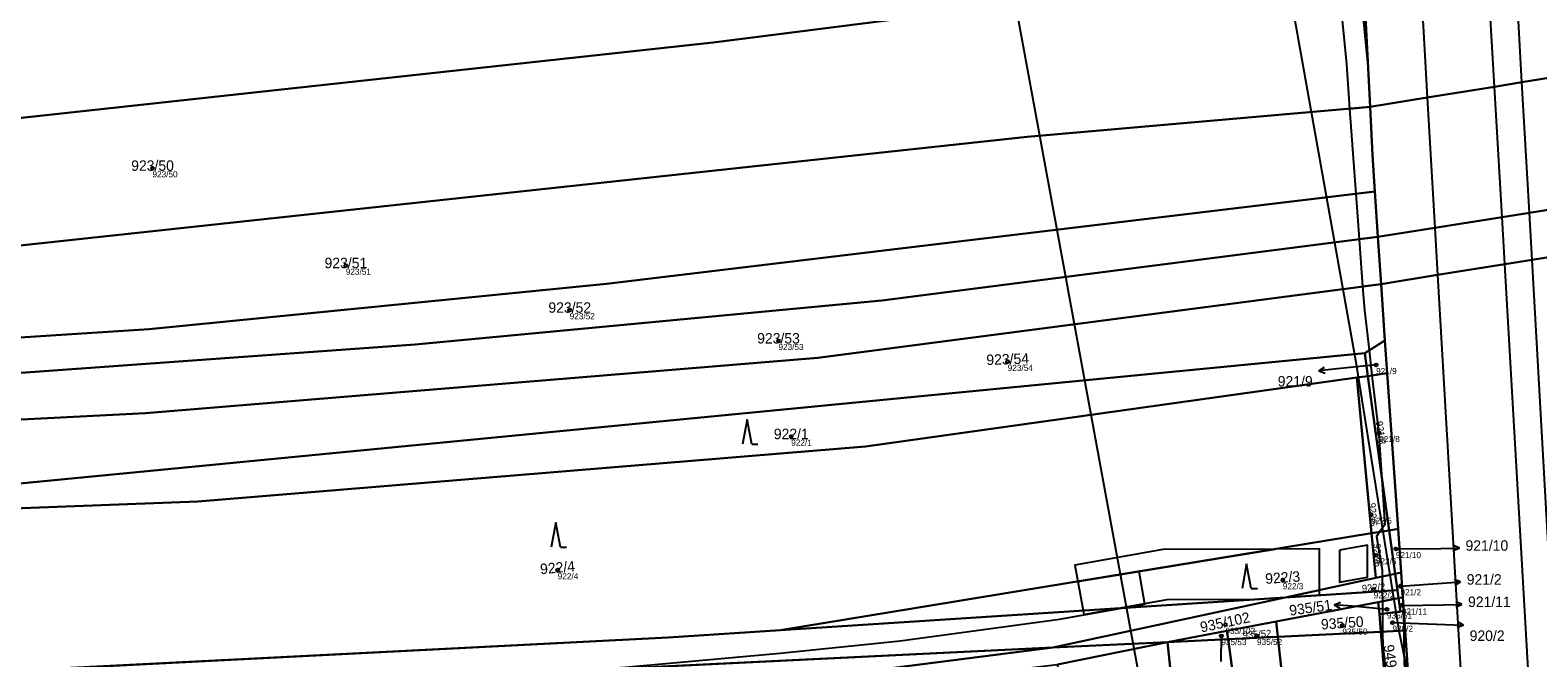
# Model space of a CAD drawing. Extents: x -603967 to -594699, y -1179315 to -1165625.
# Drawn here: x -596123.7 to -595878.2, y -1172335.5 to -1172233.4 of the extents above; entities that cross this region are included whole.
import ezdxf

# ---------------------------------------------------------------- set-up
doc = ezdxf.new("R2010")
doc.units = 0
for name, color, linetype in [('Definiční body', 7, 'Continuous'), ('Hranice parcel', 7, 'Continuous'), ('Parcelní čísla', 7, 'Continuous'), ('Polygon parcely', 7, 'Continuous'), ('Pop  PČ popisy', 7, 'Continuous'), ('Poz předměty', 7, 'Continuous'), ('Vnitřní kresba', 7, 'Continuous'), ('Věcná břemena k části', 7, 'Continuous'), ('Značky kultur', 7, 'Continuous')]:
    doc.layers.add(name, color=color, linetype=linetype)

msp = doc.modelspace()

# ---------------------------------------------------------------- linework, layer by layer
at = {"layer": 'Definiční body'}
for centre in [(-596103.76, -1172255.84994), (-596072.28, -1172271.69994), (-596035.83, -1172278.94994), (-596001.84, -1172283.95994), (-595964.51, -1172287.34994), (-595904.53, -1172287.87994), (-595999.76, -1172299.52994), (-595904.03, -1172298.93994), (-595905.33, -1172312.22994), (-595904.56, -1172318.84994), (-595901.31, -1172317.82994), (-596037.78, -1172321.27994), (-595919.72, -1172322.89994), (-595900.56, -1172323.87994), (-595904.92, -1172324.37994), (-595902.76, -1172327.66994), (-595900.33, -1172327.01994), (-595929.06, -1172330.16994), (-595910.02, -1172330.28994), (-595901.87, -1172329.80994), (-595929.73, -1172331.98994), (-595923.92, -1172331.97994)]:
    msp.add_circle(centre, 0.25, dxfattribs=at)
at = {"layer": 'Hranice parcel'}
for p, q in [((-595905.51, -1172245.87), (-595906.57, -1172224.82)), ((-595904.23, -1172267.03), (-595904.72, -1172259.65)), ((-595903.73, -1172274.7), (-595904.23, -1172267.03)), ((-595903.09, -1172283.88), (-595903.73, -1172274.7)), ((-595903.09, -1172283.88), (-595906.39, -1172285.93)), ((-595902.72, -1172289.23), (-595903.09, -1172283.88)), ((-595906.39, -1172285.93), (-596193.74, -1172313.8)), ((-595906.39, -1172285.93), (-595905.87, -1172289.68)), ((-595907.65, -1172289.93), (-595905.87, -1172289.68)), ((-595902.72, -1172289.23), (-595905.87, -1172289.68)), ((-595905.87, -1172289.68), (-595902.4, -1172314.8)), ((-595900.95, -1172314.56), (-595902.72, -1172289.23)), ((-595905.26, -1172315.27), (-595907.65, -1172289.93)), ((-595905.26, -1172315.27), (-596001.53, -1172331.07)), ((-595905.26, -1172315.27), (-595902.4, -1172314.8)), ((-595904.58, -1172322.55), (-595905.26, -1172315.27)), ((-595902.4, -1172314.8), (-595900.95, -1172314.56)), ((-595902.4, -1172314.8), (-595901.42, -1172321.87)), ((-595900.45, -1172321.66), (-595900.95, -1172314.56)), ((-595904.58, -1172322.55), (-595919.31, -1172325.73)), ((-595901.42, -1172321.87), (-595904.58, -1172322.55)), ((-595900.45, -1172321.66), (-595901.42, -1172321.87)), ((-595901.42, -1172321.87), (-595901.05, -1172324.54)), ((-595900.17, -1172325.7), (-595900.45, -1172321.66)), ((-596001.53, -1172331.07), (-595919.31, -1172325.73)), ((-595957.14, -1172333.89), (-595919.31, -1172325.73)), ((-595904.21, -1172326.47), (-595920.79, -1172329.63)), ((-595919.31, -1172325.73), (-595901.05, -1172324.54)), ((-595900.87, -1172325.83), (-595904.21, -1172326.47)), ((-595903.99, -1172328.44), (-595904.21, -1172326.47)), ((-595901.05, -1172324.54), (-595900.87, -1172325.83)), ((-595900.87, -1172325.83), (-595900.17, -1172325.7)), ((-595900.87, -1172325.83), (-595900.57, -1172328.01)), ((-595900.01, -1172327.94), (-595900.17, -1172325.7)), ((-595900.57, -1172328.01), (-595903.99, -1172328.44)), ((-595903.99, -1172328.44), (-595903.75, -1172331.3)), ((-595900.01, -1172327.94), (-595900.57, -1172328.01)), ((-595899.79, -1172331.11), (-595900.01, -1172327.94)), ((-596019.77, -1172332.25), (-596001.53, -1172331.07)), ((-595928.82, -1172331.16), (-595938.51, -1172332.99)), ((-595920.79, -1172329.63), (-595928.82, -1172331.16)), ((-595928.82, -1172331.16), (-595928.64, -1172332.51)), ((-595920.79, -1172329.63), (-595920.52, -1172332.12)), ((-595920.52, -1172332.12), (-595903.75, -1172331.3)), ((-595903.75, -1172331.3), (-595895.47, -1172399.23)), ((-596194.13, -1172341.1), (-596019.77, -1172332.25)), ((-596158.17, -1172343.65), (-595957.14, -1172333.89)), ((-595957.14, -1172333.89), (-595938.51, -1172332.99)), ((-595956.41, -1172336.65), (-595938.51, -1172332.99)), ((-595938.51, -1172332.99), (-595928.64, -1172332.51)), ((-595928.64, -1172332.51), (-595920.52, -1172332.12))]:
    msp.add_line(p, q, dxfattribs=at)
for points in [[(-595906.57, -1172224.82), (-595953.9, -1172227.9), (-596012.47, -1172235.41), (-596191.41, -1172254.87)], [(-595905.51, -1172245.87), (-595896.2, -1172244.36), (-595885.25, -1172242.59), (-595880.78, -1172241.87), (-595870.02, -1172240.13), (-595859.8, -1172238.47)], [(-596192.75, -1172275.68), (-595961.33, -1172250.76), (-595905.51, -1172245.87)], [(-595904.72, -1172259.65), (-595905.11, -1172253.75), (-595905.51, -1172245.87)], [(-596193.53, -1172287.79), (-596104.28, -1172282.03), (-596029.82, -1172274.66), (-595904.72, -1172259.65)], [(-595904.23, -1172267.03), (-595894.97, -1172265.55), (-595884.02, -1172263.8), (-595879.58, -1172263.09), (-595868.78, -1172261.36), (-595858.57, -1172259.73)], [(-596193.94, -1172294.09), (-596060.97, -1172284.56), (-595984.98, -1172277.39), (-595904.23, -1172267.03)], [(-595858.12, -1172267.42), (-595868.33, -1172269.05), (-595879.14, -1172270.77), (-595883.58, -1172271.48), (-595894.52, -1172273.23), (-595903.73, -1172274.7)], [(-596194.34, -1172300.28), (-596104.92, -1172295.74), (-595995.41, -1172286.7), (-595903.73, -1172274.7)], [(-596193.74, -1172313.8), (-596096.36, -1172310.09), (-595987.69, -1172301.14), (-595907.65, -1172289.93)], [(-595903.75, -1172331.3), (-595900.85, -1172331.16), (-595899.79, -1172331.11)], [(-595892.57, -1172559.03), (-595889.91, -1172548.74), (-595889.32, -1172536.66), (-595894.96, -1172434.47), (-595903.75, -1172331.3)], [(-595895.47, -1172399.23), (-595899.29, -1172338.29), (-595899.79, -1172331.11)], [(-596157.69, -1172348), (-596034.81, -1172343.77), (-595957.14, -1172333.89)], [(-595918.41, -1172542.08), (-595925.89, -1172452.77), (-595938.51, -1172332.99)], [(-595906.51, -1172549.65), (-595911.21, -1172477.31), (-595920.32, -1172393.96), (-595928.64, -1172332.51)], [(-595899.79, -1172554.17), (-595905.94, -1172465.46), (-595920.52, -1172332.12)]]:
    msp.add_lwpolyline(points, dxfattribs=at)
at = {"layer": 'Polygon parcely'}
for points in [[(-595906.57, -1172224.82), (-595907.75, -1172201.36), (-596008.1, -1172212.73), (-596189.99, -1172232.87), (-596191.41, -1172254.87), (-596012.47, -1172235.41), (-595953.9, -1172227.9)], [(-595880.78, -1172241.87), (-595870.02, -1172240.13), (-595859.8, -1172238.47), (-595861.02, -1172217.5), (-595871.25, -1172219.15), (-595881.97, -1172220.87), (-595886.47, -1172221.59), (-595897.42, -1172223.35), (-595906.57, -1172224.82), (-595905.51, -1172245.87), (-595896.2, -1172244.36), (-595885.25, -1172242.59)], [(-596191.41, -1172254.87), (-596192.75, -1172275.68), (-595961.33, -1172250.76), (-595905.51, -1172245.87), (-595906.57, -1172224.82), (-595953.9, -1172227.9), (-596012.47, -1172235.41)], [(-595884.02, -1172263.8), (-595879.58, -1172263.09), (-595868.78, -1172261.36), (-595858.57, -1172259.73), (-595858.94, -1172253.33), (-595859.8, -1172238.47), (-595870.02, -1172240.13), (-595880.78, -1172241.87), (-595885.25, -1172242.59), (-595896.2, -1172244.36), (-595905.51, -1172245.87), (-595905.11, -1172253.75), (-595904.72, -1172259.65), (-595904.23, -1172267.03), (-595894.97, -1172265.55)], [(-596193.53, -1172287.79), (-596104.28, -1172282.03), (-596029.82, -1172274.66), (-595904.72, -1172259.65), (-595905.11, -1172253.75), (-595905.51, -1172245.87), (-595961.33, -1172250.76), (-596192.75, -1172275.68)], [(-595904.23, -1172267.03), (-595904.72, -1172259.65), (-596029.82, -1172274.66), (-596104.28, -1172282.03), (-596193.53, -1172287.79), (-596193.94, -1172294.09), (-596060.97, -1172284.56), (-595984.98, -1172277.39)], [(-595858.12, -1172267.42), (-595858.57, -1172259.73), (-595868.78, -1172261.36), (-595879.58, -1172263.09), (-595884.02, -1172263.8), (-595894.97, -1172265.55), (-595904.23, -1172267.03), (-595903.73, -1172274.7), (-595894.52, -1172273.23), (-595883.58, -1172271.48), (-595879.14, -1172270.77), (-595868.33, -1172269.05)], [(-595903.73, -1172274.7), (-595904.23, -1172267.03), (-595984.98, -1172277.39), (-596060.97, -1172284.56), (-596193.94, -1172294.09), (-596194.34, -1172300.28), (-596104.92, -1172295.74), (-595995.41, -1172286.7)], [(-595903.09, -1172283.88), (-595903.73, -1172274.7), (-595995.41, -1172286.7), (-596104.92, -1172295.74), (-596194.34, -1172300.28), (-596195.22, -1172313.87), (-596193.74, -1172313.8), (-595906.39, -1172285.93)], [(-595902.72, -1172289.23), (-595903.09, -1172283.88), (-595906.39, -1172285.93), (-595905.87, -1172289.68)], [(-595905.87, -1172289.68), (-595906.39, -1172285.93), (-596193.74, -1172313.8), (-596096.36, -1172310.09), (-595987.69, -1172301.14), (-595907.65, -1172289.93)], [(-595905.26, -1172315.27), (-595902.4, -1172314.8), (-595905.87, -1172289.68), (-595907.65, -1172289.93)], [(-595902.4, -1172314.8), (-595900.95, -1172314.56), (-595902.72, -1172289.23), (-595905.87, -1172289.68)], [(-595905.26, -1172315.27), (-595907.65, -1172289.93), (-595987.69, -1172301.14), (-596096.36, -1172310.09), (-596193.74, -1172313.8), (-596194.13, -1172341.1), (-596019.77, -1172332.25), (-596001.53, -1172331.07)], [(-596001.53, -1172331.07), (-595919.31, -1172325.73), (-595904.58, -1172322.55), (-595905.26, -1172315.27)], [(-595901.42, -1172321.87), (-595902.4, -1172314.8), (-595905.26, -1172315.27), (-595904.58, -1172322.55)], [(-595901.42, -1172321.87), (-595900.45, -1172321.66), (-595900.95, -1172314.56), (-595902.4, -1172314.8)], [(-595919.31, -1172325.73), (-595901.05, -1172324.54), (-595901.42, -1172321.87), (-595904.58, -1172322.55)], [(-595901.42, -1172321.87), (-595901.05, -1172324.54), (-595900.87, -1172325.83), (-595900.17, -1172325.7), (-595900.45, -1172321.66)], [(-596194.86, -1172345.53), (-596158.17, -1172343.65), (-595957.14, -1172333.89), (-595919.31, -1172325.73), (-596001.53, -1172331.07), (-596019.77, -1172332.25), (-596194.13, -1172341.1), (-596196.99, -1172341.21), (-596199.78, -1172341.32), (-596198.52, -1172345.99)], [(-595957.14, -1172333.89), (-595938.51, -1172332.99), (-595928.82, -1172331.16), (-595920.79, -1172329.63), (-595904.21, -1172326.47), (-595900.87, -1172325.83), (-595901.05, -1172324.54), (-595919.31, -1172325.73)], [(-595920.52, -1172332.12), (-595903.75, -1172331.3), (-595903.99, -1172328.44), (-595904.21, -1172326.47), (-595920.79, -1172329.63)], [(-595900.87, -1172325.83), (-595904.21, -1172326.47), (-595903.99, -1172328.44), (-595900.57, -1172328.01)], [(-595900.57, -1172328.01), (-595900.01, -1172327.94), (-595900.17, -1172325.7), (-595900.87, -1172325.83)], [(-595900.01, -1172327.94), (-595900.57, -1172328.01), (-595903.99, -1172328.44), (-595903.75, -1172331.3), (-595900.85, -1172331.16), (-595899.79, -1172331.11)], [(-595928.82, -1172331.16), (-595938.51, -1172332.99), (-595928.64, -1172332.51)], [(-595928.64, -1172332.51), (-595920.52, -1172332.12), (-595920.79, -1172329.63), (-595928.82, -1172331.16)], [(-595894.96, -1172434.47), (-595903.75, -1172331.3), (-595920.52, -1172332.12), (-595905.94, -1172465.46), (-595899.79, -1172554.17), (-595892.57, -1172559.03), (-595889.91, -1172548.74), (-595889.32, -1172536.66)], [(-595895.47, -1172399.23), (-595899.29, -1172338.29), (-595899.79, -1172331.11), (-595900.85, -1172331.16), (-595903.75, -1172331.3)], [(-595887.08, -1172537.79), (-595893.23, -1172433.55), (-595894.94, -1172407.61), (-595895.47, -1172399.23), (-595903.75, -1172331.3), (-595894.96, -1172434.47), (-595889.32, -1172536.66), (-595889.91, -1172548.74), (-595892.57, -1172559.03), (-595890.44, -1172561.15), (-595889.81, -1172560.41), (-595887.37, -1172550.11)], [(-596157.69, -1172348), (-596034.81, -1172343.77), (-595957.14, -1172333.89), (-596158.17, -1172343.65)], [(-595982.23, -1172340.15), (-595973.49, -1172338.64), (-595956.41, -1172336.65), (-595938.51, -1172332.99), (-595957.14, -1172333.89), (-596034.81, -1172343.77), (-596157.69, -1172348), (-596157.31, -1172351.36), (-596143.3, -1172350.24), (-596136.49, -1172350.13), (-596123.02, -1172349.7), (-596110.99, -1172349.51), (-596103.83, -1172349.38), (-596096.98, -1172349.13), (-596089.05, -1172348.79), (-596071.19, -1172348.02), (-596052.73, -1172347.42), (-596034.37, -1172346.55), (-596027.89, -1172345.98), (-596021.5, -1172345.1), (-596013.26, -1172344.03), (-596006.34, -1172343.33), (-595998.25, -1172342.44), (-595990.99, -1172341.19)], [(-595918.41, -1172542.08), (-595925.89, -1172452.77), (-595938.51, -1172332.99), (-595956.41, -1172336.65), (-595938.08, -1172531.05)], [(-595920.32, -1172393.96), (-595928.64, -1172332.51), (-595938.51, -1172332.99), (-595925.89, -1172452.77), (-595918.41, -1172542.08), (-595914.5, -1172544.27), (-595906.51, -1172549.65), (-595911.21, -1172477.31)], [(-595899.79, -1172554.17), (-595905.94, -1172465.46), (-595920.52, -1172332.12), (-595928.64, -1172332.51), (-595920.32, -1172393.96), (-595911.21, -1172477.31), (-595906.51, -1172549.65)]]:
    msp.add_lwpolyline(points, close=True, dxfattribs=at)
msp.add_lwpolyline([(-595868.33, -1172269.05), (-595879.14, -1172270.77), (-595883.58, -1172271.48), (-595894.52, -1172273.23), (-595903.73, -1172274.7), (-595903.09, -1172283.88), (-595902.72, -1172289.23), (-595900.95, -1172314.56), (-595900.45, -1172321.66), (-595900.17, -1172325.7), (-595900.01, -1172327.94), (-595899.79, -1172331.11), (-595899.29, -1172338.29), (-595895.47, -1172399.23), (-595894.94, -1172407.61), (-595884.6, -1172495.44), (-595881.58, -1172567.78), (-595887.7, -1172563.88), (-595887.85, -1172569.82), (-595877.77, -1172576.26)], dxfattribs=at)
at = {"layer": 'Pop  PČ popisy'}
for p, q in [((-595913.875, -1172288.834), (-595912.931, -1172288.231)), ((-595910.89, -1172288.52), (-595913.875, -1172288.834)), ((-595913.875, -1172288.834), (-595912.826, -1172289.227)), ((-595904.53, -1172287.88), (-595910.89, -1172288.52)), ((-595901.31, -1172317.83), (-595893.97, -1172317.73)), ((-595893.97, -1172317.73), (-595890.969, -1172317.678)), ((-595890.969, -1172317.678), (-595891.98, -1172317.194)), ((-595890.969, -1172317.678), (-595891.962, -1172318.196)), ((-595900.56, -1172323.88), (-595893.76, -1172323.41)), ((-595893.76, -1172323.41), (-595890.766, -1172323.201)), ((-595890.766, -1172323.201), (-595891.8, -1172322.771)), ((-595890.766, -1172323.201), (-595891.73, -1172323.77)), ((-595911.38, -1172326.898), (-595910.338, -1172326.487)), ((-595890.559, -1172326.848), (-595891.57, -1172326.364)), ((-595908.39, -1172327.16), (-595911.38, -1172326.898)), ((-595911.38, -1172326.898), (-595910.426, -1172327.485)), ((-595902.76, -1172327.67), (-595908.39, -1172327.16)), ((-595900.33, -1172327.02), (-595893.56, -1172326.9)), ((-595893.56, -1172326.9), (-595890.559, -1172326.848)), ((-595890.559, -1172326.848), (-595891.552, -1172327.366)), ((-595901.87, -1172329.81), (-595893.3, -1172330.12)), ((-595893.3, -1172330.12), (-595890.301, -1172330.225)), ((-595890.301, -1172330.225), (-595891.319, -1172330.69)), ((-595890.301, -1172330.225), (-595891.284, -1172329.689)), ((-595929.73, -1172331.99), (-595929.79, -1172336.17))]:
    msp.add_line(p, q, dxfattribs=at)
at = {"layer": 'Poz předměty'}
for p, q in [((-595901.88, -1172562.6), (-596170.28, -1171103.82)), ((-596119.4, -1171103.94), (-595907.87, -1172287.12)), ((-595907.87, -1172287.12), (-595903.43, -1172314.97)), ((-595903.43, -1172314.97), (-595900.85, -1172331.16)), ((-595900.85, -1172331.16), (-595872.26, -1172467))]:
    msp.add_line(p, q, dxfattribs=at)
at = {"layer": 'Vnitřní kresba'}
for p, q in [((-595880.78, -1172241.87), (-595881.97, -1172220.87)), ((-595897.42, -1172223.35), (-595896.2, -1172244.36)), ((-595885.25, -1172242.59), (-595886.47, -1172221.59)), ((-595884.02, -1172263.8), (-595885.25, -1172242.59)), ((-595879.58, -1172263.09), (-595880.78, -1172241.87)), ((-595896.2, -1172244.36), (-595894.97, -1172265.55)), ((-595883.58, -1172271.48), (-595884.02, -1172263.8)), ((-595879.14, -1172270.77), (-595879.58, -1172263.09)), ((-595894.97, -1172265.55), (-595894.52, -1172273.23)), ((-595872.26, -1172467), (-595883.58, -1172271.48)), ((-595874.36, -1172355.21), (-595879.14, -1172270.77)), ((-595894.52, -1172273.23), (-595881.79, -1172492.57))]:
    msp.add_line(p, q, dxfattribs=at)
at = {"layer": 'Věcná břemena k části'}
for points in [[(-595909.37, -1172238.94), (-595908.84, -1172246.16), (-595905.51, -1172245.87), (-595905.84, -1172239.34), (-595905.89, -1172238.64), (-595907.21, -1172224.86), (-595910.7, -1172225.09)], [(-595907.83, -1172260.02), (-595904.72, -1172259.65), (-595905.11, -1172253.75), (-595905.51, -1172245.87), (-595908.84, -1172246.16)], [(-595907.29, -1172267.42), (-595904.23, -1172267.03), (-595904.72, -1172259.65), (-595907.83, -1172260.02)], [(-595906.72, -1172275.09), (-595903.73, -1172274.7), (-595904.23, -1172267.03), (-595907.29, -1172267.42)], [(-595902.72, -1172289.23), (-595903.09, -1172283.88), (-595903.73, -1172274.7), (-595906.72, -1172275.09), (-595906.44, -1172278.97), (-595905.68, -1172285.49), (-595905.2, -1172289.58)], [(-595905.2, -1172289.58), (-595904.14, -1172298.62), (-595903.66, -1172305.69), (-595903.1, -1172313.88), (-595903.96, -1172315.06), (-595902.4, -1172314.8), (-595900.95, -1172314.56), (-595902.72, -1172289.23)], [(-595901.42, -1172321.87), (-595902.4, -1172314.8), (-595903.96, -1172315.06), (-595904.49, -1172315.79), (-595903.54, -1172321.22), (-595903.53, -1172322.32)], [(-595953.1, -1172323.12), (-595920.98, -1172317.85), (-595939.28, -1172317.9), (-595953.58, -1172320.49)], [(-595913.72, -1172324.52), (-595913.74, -1172317.83), (-595920.98, -1172317.85), (-595943.12, -1172321.48), (-595953.1, -1172323.12), (-595952.24, -1172327.87), (-595952.12, -1172328.51), (-595946.48, -1172327.49), (-595938.54, -1172326.06), (-595923.74, -1172326.02), (-595919.31, -1172325.73)], [(-595910.5, -1172318.01), (-595910.48, -1172323.21), (-595905.91, -1172322.41), (-595905.93, -1172317.21)], [(-595943.12, -1172321.48), (-596001.53, -1172331.07), (-596019.77, -1172332.25), (-596194.13, -1172341.1), (-596196.99, -1172341.21), (-596199.78, -1172341.32), (-596199.63, -1172341.86), (-596191.92, -1172341.99), (-596173.07, -1172342.68), (-596158.83, -1172343.68), (-596158.17, -1172343.65), (-596035.82, -1172337.71), (-596026.77, -1172337.06), (-596001.57, -1172334.8), (-595982.01, -1172332.77), (-595956.1, -1172329.23), (-595945.97, -1172327.46), (-595942.19, -1172326.8)], [(-595900.87, -1172325.83), (-595901.05, -1172324.54), (-595901.42, -1172321.87), (-595903.53, -1172322.32), (-595903.52, -1172324.7), (-595903.51, -1172326.34)], [(-595913.72, -1172324.52), (-595919.31, -1172325.73), (-595913.72, -1172325.37)], [(-595898.23, -1172376.61), (-595899.95, -1172334.75), (-595899.97, -1172331.12), (-595899.99, -1172328.19), (-595900.01, -1172327.94), (-595900.57, -1172328.01), (-595900.87, -1172325.83), (-595903.51, -1172326.34), (-595903.49, -1172328.38), (-595903.47, -1172331.29), (-595903.46, -1172333.71)], [(-595903.46, -1172333.71), (-595903.45, -1172334.81), (-595903.45, -1172334.83), (-595900.58, -1172404.65), (-595899.23, -1172430.89), (-595897.84, -1172470.47), (-595896.42, -1172503.69), (-595895.24, -1172537.54), (-595894.96, -1172557.42), (-595892.57, -1172559.03), (-595891.42, -1172560.17), (-595891.5, -1172554.88), (-595891.74, -1172537.46), (-595892.92, -1172503.55), (-595894.34, -1172470.33), (-595895.73, -1172430.73), (-595896.42, -1172417.36), (-595897.08, -1172404.49), (-595898.23, -1172376.61)]]:
    msp.add_lwpolyline(points, close=True, dxfattribs=at)
at = {"layer": 'Značky kultur'}
for p, q in [((-596006.93, -1172296.75), (-596007.68, -1172300.75)), ((-596006.18, -1172300.75), (-596006.93, -1172296.75)), ((-596006.18, -1172300.75), (-596005.184, -1172300.75)), ((-596038.07, -1172313.54), (-596038.82, -1172317.54)), ((-596037.32, -1172317.54), (-596038.07, -1172313.54)), ((-596037.32, -1172317.54), (-596036.324, -1172317.54)), ((-595925.61, -1172320.24), (-595926.36, -1172324.24)), ((-595924.86, -1172324.24), (-595925.61, -1172320.24)), ((-595924.86, -1172324.24), (-595923.864, -1172324.24))]:
    msp.add_line(p, q, dxfattribs=at)

# ---------------------------------------------------------------- texts
at = {"layer": 'Definiční body'}
for s, p in [('923/50', (-596103.76, -1172257.339)), ('923/51', (-596072.28, -1172273.189)), ('923/52', (-596035.83, -1172280.439)), ('923/53', (-596001.84, -1172285.449)), ('923/54', (-595964.51, -1172288.839)), ('921/9', (-595904.53, -1172289.369)), ('921/8', (-595904.03, -1172300.429)), ('922/1', (-595999.76, -1172301.019)), ('922/5', (-595905.33, -1172313.719)), ('921/10', (-595901.31, -1172319.319)), ('922/6', (-595904.56, -1172320.339)), ('922/4', (-596037.78, -1172322.769)), ('922/3', (-595919.72, -1172324.389)), ('922/2', (-595904.92, -1172325.869)), ('921/2', (-595900.56, -1172325.369)), ('935/51', (-595902.76, -1172329.159)), ('921/11', (-595900.33, -1172328.509)), ('935/102', (-595929.06, -1172331.659)), ('935/50', (-595910.02, -1172331.779)), ('920/2', (-595901.87, -1172331.299)), ('935/53', (-595929.73, -1172333.479)), ('935/52', (-595923.92, -1172333.469))]:
    msp.add_text(s, height=0.999996, dxfattribs=at).set_placement(p)
at = {"layer": 'Parcelní čísla'}
for s, p in [('923/50', (-596107.226, -1172256.275)), ('923/51', (-596075.746, -1172272.125)), ('923/52', (-596039.296, -1172279.375)), ('923/53', (-596005.306, -1172284.385)), ('921/9', (-595920.542, -1172291.385)), ('922/1', (-596002.596, -1172299.955)), ('921/10', (-595889.97, -1172318.115)), ('921/2', (-595889.77, -1172323.635)), ('921/11', (-595889.56, -1172327.275)), ('920/2', (-595889.3, -1172332.795))]:
    msp.add_text(s, height=1.699998, dxfattribs=at).set_placement(p)
for s, height, rotation, p in [('923/54', 1.699998, 2, (-595967.959, -1172287.895)), ('921/8', 1.14, 278, (-595904.576, -1172297.096)), ('922/5', 1.14, 274, (-595905.746, -1172310.352)), ('922/6', 1.14, 273, (-595904.944, -1172316.965)), ('922/4', 1.699998, 5, (-596040.568, -1172321.95)), ('922/3', 1.699998, 4, (-595922.519, -1172323.521)), ('922/2', 1.14, 5, (-595906.789, -1172324.829)), ('935/51', 1.699998, 8, (-595918.536, -1172328.705)), ('935/102', 1.699998, 12, (-595932.978, -1172331.437)), ('935/50', 1.699998, 4, (-595913.448, -1172330.955)), ('935/52', 1.14, 4, (-595926.218, -1172332.426)), ('949/3', 1.699998, 278, (-595903.335, -1172333.51))]:
    msp.add_text(s, height=height, rotation=rotation, dxfattribs=at).set_placement(p)

doc.saveas('drawing.dxf')
